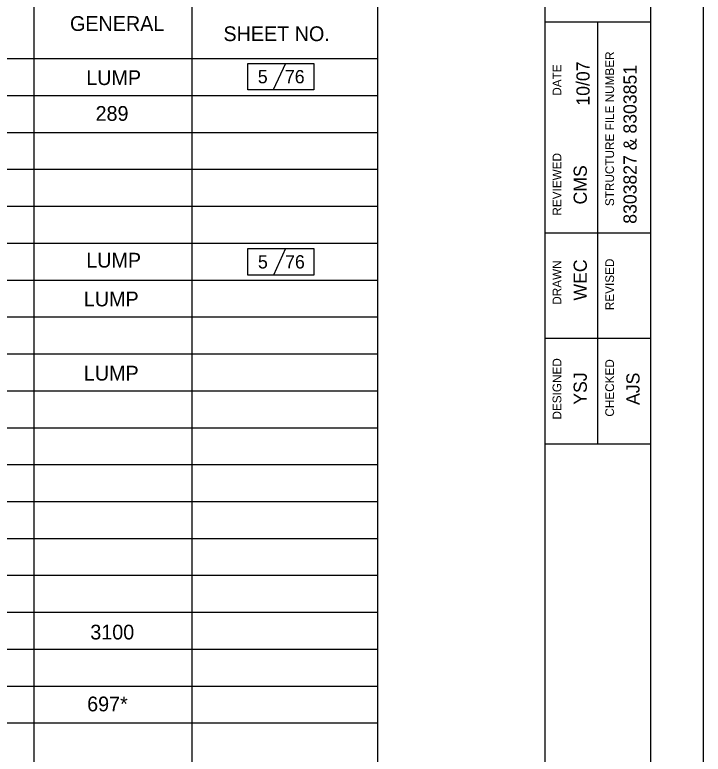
# Model space of a CAD drawing. Extents: x 0 to 34, y 0 to 22.
# Drawn here: x 27.47 to 34, y 11.06 to 18.07 of the extents above; entities that cross this region are included whole.
import ezdxf

# ---------------------------------------------------------------- set-up
doc = ezdxf.new("R2010")
doc.units = 0
for name, color, linetype in [('BR_P_Gen_Text', 7, 'Continuous'), ('SH_Border', 7, 'Continuous'), ('SH_Cut_Line', 7, 'Continuous'), ('SH_Data', 7, 'Continuous'), ('SH_Text', 7, 'Continuous')]:
    doc.layers.add(name, color=color, linetype=linetype)

msp = doc.modelspace()

# ---------------------------------------------------------------- linework, layer by layer
at = {"layer": 'BR_P_Gen_Text'}
for p, q in [((30.0366, 17.6055), (29.921, 17.3556)), ((30.0384, 15.8496), (29.9228, 15.5997))]:
    msp.add_line(p, q, dxfattribs=at)
for points in [[(29.6796, 17.6055), (30.3057, 17.6055), (30.3057, 17.3556), (29.6796, 17.3556)], [(29.6796, 17.6055), (30.3057, 17.6055), (30.3057, 17.3556), (29.6796, 17.3556)], [(29.6814, 15.8496), (30.3075, 15.8496), (30.3075, 15.5997), (29.6814, 15.5997)], [(29.6814, 15.8496), (30.3075, 15.8496), (30.3075, 15.5997), (29.6814, 15.5997)]]:
    msp.add_lwpolyline(points, close=True, dxfattribs=at)
at = {"layer": 'SH_Border'}
for p, q in [((32.5, 0.5), (32.5, 21.5)), ((32.5, 0.5), (32.5, 21.5)), ((32.5, 0.5), (32.5, 21.5)), ((32.5, 18), (33.5, 18)), ((32.5, 18), (33.5, 18)), ((32.5, 18), (33.5, 18)), ((33, 14), (33, 18)), ((33, 14), (33, 18)), ((33, 14), (33, 18)), ((32.5, 16), (33.5, 16)), ((32.5, 16), (33.5, 16)), ((32.5, 16), (33.5, 16)), ((32.5, 15), (33.5, 15)), ((32.5, 15), (33.5, 15)), ((32.5, 15), (33.5, 15)), ((32.5, 14), (33.5, 14)), ((32.5, 14), (33.5, 14)), ((32.5, 14), (33.5, 14))]:
    msp.add_line(p, q, dxfattribs=at)
msp.add_lwpolyline([(2, 21.5), (33.5, 21.5), (33.5, 0.5), (2, 0.5)], close=True, dxfattribs=at)
at = {"layer": 'SH_Cut_Line'}
msp.add_lwpolyline([(0, 22), (34, 22), (34, 0), (0, 0)], close=True, dxfattribs=at)
at = {"layer": 'SH_Text'}
for p, q in [((30.91, 19.3096), (30.91, 5.0521)), ((27.6498, 18.3521), (27.6498, 5.0521)), ((29.1498, 18.3521), (29.1498, 5.0521)), ((3.59, 17.6521), (30.91, 17.6521)), ((3.59, 17.3021), (30.91, 17.3021)), ((3.59, 16.9521), (30.91, 16.9521)), ((3.59, 16.6021), (30.91, 16.6021)), ((3.59, 16.2521), (30.91, 16.2521)), ((3.59, 15.9021), (30.91, 15.9021)), ((3.59, 15.5521), (30.91, 15.5521)), ((3.59, 15.2021), (30.91, 15.2021)), ((3.59, 14.8521), (30.91, 14.8521)), ((3.59, 14.5021), (30.91, 14.5021)), ((3.59, 14.1521), (30.91, 14.1521)), ((3.59, 13.8021), (30.91, 13.8021)), ((3.59, 13.4521), (30.91, 13.4521)), ((3.59, 13.1021), (30.91, 13.1021)), ((3.59, 12.7521), (30.91, 12.7521)), ((3.59, 12.4021), (30.91, 12.4021)), ((3.59, 12.0521), (30.91, 12.0521)), ((3.59, 11.7021), (30.91, 11.7021)), ((3.59, 11.3521), (30.91, 11.3521))]:
    msp.add_line(p, q, dxfattribs=at)

# ---------------------------------------------------------------- texts
at = {"layer": 'BR_P_Gen_Text'}
for s, p in [(' 5', (29.7275, 17.4176)), ('76', (30.0314, 17.4176)), (' 5', (29.7292, 15.6617)), ('76', (30.0332, 15.6617))]:
    msp.add_text(s, height=0.12587, dxfattribs=at).set_placement(p)
at = {"layer": 'SH_Data'}
for s, height, p in [('STRUCTURE FILE NUMBER', 0.0833, (33.1542, 16.253)), ('10/07', 0.125, (32.9221, 17.206)), ('DATE', 0.0833, (32.6542, 17.2997)), ('8303827 & 8303851', 0.125, (33.3684, 16.0856)), ('REVIEWED', 0.0833, (32.6542, 16.1627)), ('CMS', 0.125, (32.8958, 16.2687)), ('DRAWN', 0.0833, (32.6542, 15.3177)), ('WEC', 0.125, (32.8958, 15.3576)), ('REVISED', 0.0833, (33.1542, 15.2665)), ('DESIGNED', 0.0833, (32.6542, 14.2292)), ('CHECKED', 0.0833, (33.1542, 14.2567)), ('YSJ', 0.125, (32.8958, 14.3699)), ('AJS', 0.125, (33.3958, 14.3675))]:
    msp.add_text(s, height=height, rotation=90, dxfattribs=at).set_placement(p)
at = {"layer": 'SH_Text'}
for s, p in [('GENERAL', (27.993, 17.9142)), ('SHEET NO.', (29.4486, 17.8177)), ('LUMP', (28.1468, 17.4009)), ('289', (28.2355, 17.0618)), ('LUMP', (28.1468, 15.6702)), ('LUMP', (28.1242, 15.3025)), ('LUMP', (28.1242, 14.599)), ('3100', (28.1856, 12.1438)), ('697*', (28.1558, 11.4624))]:
    msp.add_text(s, height=0.14, dxfattribs=at).set_placement(p)

doc.saveas('drawing.dxf')
